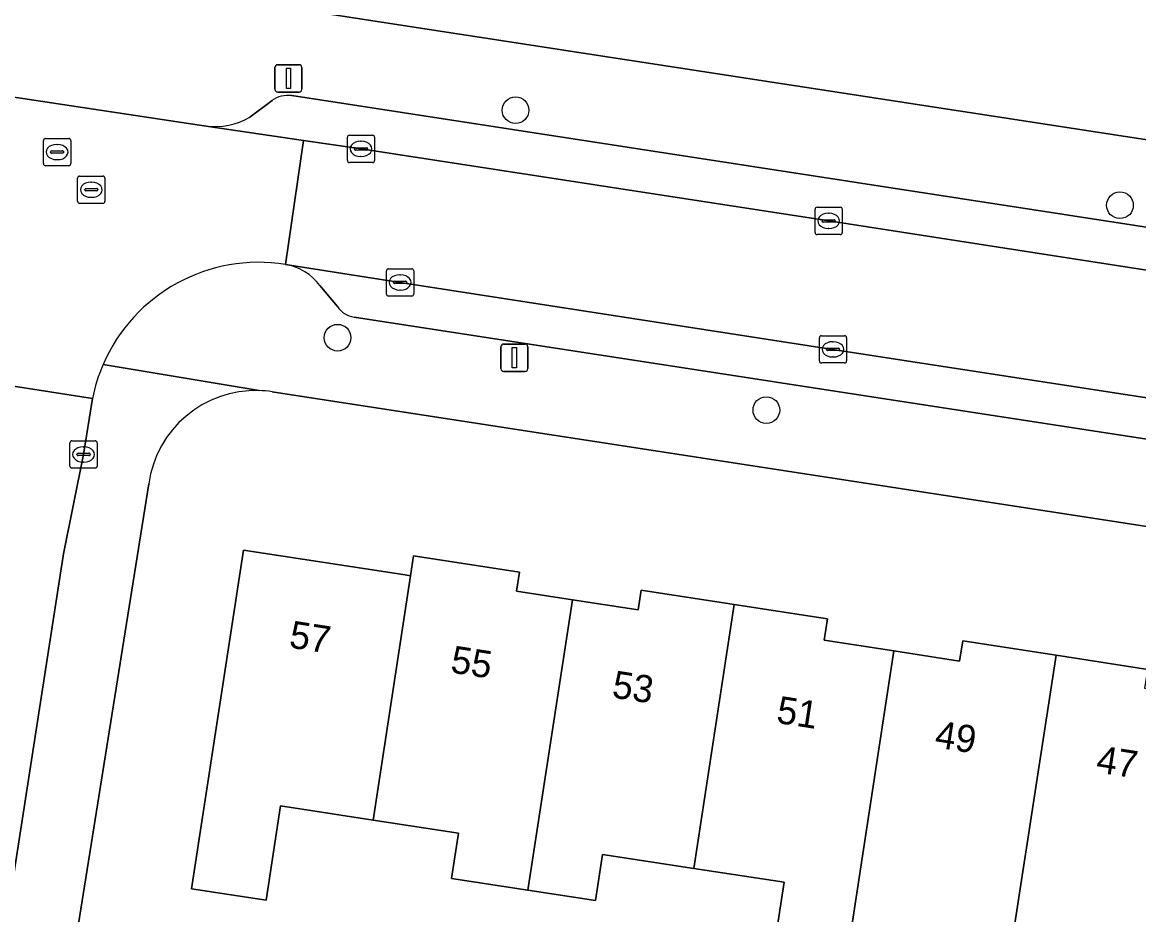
# Model space of a CAD drawing. Extents: x 161483 to 162250, y 379484 to 380833.
# Drawn here: x 161922.95 to 161963.9, y 380518.15 to 380550.89 of the extents above; entities that cross this region are included whole.
import ezdxf

# ---------------------------------------------------------------- set-up
doc = ezdxf.new("R2010")
doc.units = 0
for name, color, linetype in [('IMGEO_Boom', 7, 'Continuous'), ('IMGEO_Erf', 7, 'Continuous'), ('IMGEO_Kolk', 7, 'Continuous'), ('IMGEO_Lichtmast', 7, 'Continuous'), ('IMGEO_Pand', 7, 'Continuous'), ('IMGEO_Pand_nummerreeks', 7, 'Continuous'), ('IMGEO_Parkeervlak_open', 7, 'Continuous'), ('IMGEO_Rijbaan_lokaal_open', 7, 'Continuous'), ('IMGEO_Rioolput', 7, 'Continuous'), ('IMGEO_Voetpad_open', 7, 'Continuous')]:
    doc.layers.add(name, color=color, linetype=linetype)

msp = doc.modelspace()

# ---------------------------------------------------------------- linework, layer by layer
at = {"layer": 'IMGEO_Boom'}
for centre in [(161941.042, 380547.667), (161963.213, 380544.18), (161934.512, 380539.321), (161950.241, 380536.664)]:
    msp.add_circle(centre, 0.489, dxfattribs=at)
at = {"layer": 'IMGEO_Erf'}
for points in [[(161933.1, 380551.357), (161963.411, 380546.705), (161989.926, 380542.639)], [(162001.728, 380523.906), (162001.658, 380524.62), (162001.144, 380525.735), (162000.674, 380526.189), (162000.627, 380526.234), (162000, 380526.588), (161998.738, 380527.044), (161986.998, 380528.881), (161932.112, 380537.338)], [(161927.582, 380533.959), (161924.124, 380512.314)], [(161950.629, 380517.592), (161950.898, 380519.337), (161947.576, 380519.847), (161944.231, 380520.361), (161943.971, 380518.666), (161941.487, 380519.048), (161938.688, 380519.478), (161938.943, 380521.14), (161935.813, 380521.621), (161932.42, 380522.143), (161931.888, 380518.678), (161929.148, 380519.1), (161931.059, 380531.529), (161936.985, 380530.618), (161937.189, 380530.587), (161937.301, 380531.315), (161941.187, 380530.718), (161941.08, 380530.019), (161943.124, 380529.705), (161945.54, 380529.334), (161945.651, 380530.056), (161949.063, 380529.531), (161952.481, 380529.006), (161952.36, 380528.221), (161954.923, 380527.827), (161957.332, 380527.456), (161957.446, 380528.194), (161960.869, 380527.668), (161964.235, 380527.151)]]:
    msp.add_lwpolyline(points, dxfattribs=at)
for centre, radius, start, end in [((161931.515, 380533.412), 3.971, 88.3365, 172.0829), ((161931.527, 380533.506), 3.876, 81.3232, 88.4809)]:
    msp.add_arc(centre, radius, start, end, dxfattribs=at)
at = {"layer": 'IMGEO_Kolk'}
for p, q in [((161934.87, 380545.822), (161934.87, 380546.674)), ((161934.945, 380546.748), (161935.797, 380546.748)), ((161935.871, 380546.674), (161935.871, 380545.822)), ((161935.129, 380546.242), (161935.129, 380546.254)), ((161935.172, 380546.291), (161935.57, 380546.291)), ((161935.358, 380546.528), (161935.383, 380546.528)), ((161935.613, 380546.254), (161935.613, 380546.242)), ((161935.567, 380546.205), (161935.169, 380546.205)), ((161935.381, 380545.968), (161935.356, 380545.968)), ((161935.797, 380545.748), (161934.945, 380545.748)), ((161952.027, 380543.178), (161952.027, 380544.03)), ((161952.102, 380544.104), (161952.954, 380544.104)), ((161952.515, 380543.884), (161952.54, 380543.884)), ((161953.028, 380544.03), (161953.028, 380543.178)), ((161952.286, 380543.598), (161952.286, 380543.61)), ((161952.724, 380543.561), (161952.326, 380543.561)), ((161952.329, 380543.647), (161952.727, 380543.647)), ((161952.77, 380543.61), (161952.77, 380543.598)), ((161952.954, 380543.104), (161952.102, 380543.104)), ((161952.538, 380543.324), (161952.513, 380543.324)), ((161936.304, 380540.923), (161936.304, 380541.775)), ((161936.379, 380541.849), (161937.231, 380541.849)), ((161937.305, 380541.775), (161937.305, 380540.923)), ((161936.563, 380541.343), (161936.563, 380541.355)), ((161936.606, 380541.392), (161937.004, 380541.392)), ((161936.792, 380541.629), (161936.817, 380541.629)), ((161937.047, 380541.355), (161937.047, 380541.343)), ((161937.001, 380541.306), (161936.603, 380541.306)), ((161936.815, 380541.069), (161936.79, 380541.069)), ((161937.231, 380540.849), (161936.379, 380540.849)), ((161952.185, 380538.466), (161952.185, 380539.318)), ((161952.26, 380539.392), (161953.112, 380539.392)), ((161953.186, 380539.318), (161953.186, 380538.466)), ((161952.444, 380538.886), (161952.444, 380538.898)), ((161952.487, 380538.935), (161952.885, 380538.935)), ((161952.673, 380539.172), (161952.698, 380539.172)), ((161952.928, 380538.898), (161952.928, 380538.886)), ((161952.882, 380538.849), (161952.484, 380538.849)), ((161952.696, 380538.612), (161952.671, 380538.612)), ((161953.112, 380538.392), (161952.26, 380538.392)), ((161924.692, 380534.61), (161924.692, 380535.462)), ((161924.767, 380535.536), (161925.619, 380535.536)), ((161925.18, 380535.316), (161925.205, 380535.316)), ((161925.693, 380535.462), (161925.693, 380534.61)), ((161924.951, 380535.03), (161924.951, 380535.042)), ((161925.389, 380534.993), (161924.991, 380534.993)), ((161924.994, 380535.079), (161925.392, 380535.079)), ((161925.435, 380535.042), (161925.435, 380535.03)), ((161925.619, 380534.536), (161924.767, 380534.536)), ((161925.203, 380534.756), (161925.178, 380534.756))]:
    msp.add_line(p, q, dxfattribs=at)
for points in [[(161934.87, 380545.822), (161934.87, 380546.674)], [(161934.945, 380546.748), (161935.797, 380546.748)], [(161935.871, 380546.674), (161935.871, 380545.822)], [(161935.797, 380545.748), (161934.945, 380545.748)], [(161952.027, 380543.178), (161952.027, 380544.03)], [(161952.102, 380544.104), (161952.954, 380544.104)], [(161953.028, 380544.03), (161953.028, 380543.178)], [(161952.954, 380543.104), (161952.102, 380543.104)], [(161936.304, 380540.923), (161936.304, 380541.775)], [(161936.379, 380541.849), (161937.231, 380541.849)], [(161937.305, 380541.775), (161937.305, 380540.923)], [(161937.231, 380540.849), (161936.379, 380540.849)], [(161952.185, 380538.466), (161952.185, 380539.318)], [(161952.26, 380539.392), (161953.112, 380539.392)], [(161953.186, 380539.318), (161953.186, 380538.466)], [(161953.112, 380538.392), (161952.26, 380538.392)], [(161924.692, 380534.61), (161924.692, 380535.462)], [(161924.767, 380535.536), (161925.619, 380535.536)], [(161925.693, 380535.462), (161925.693, 380534.61)], [(161925.619, 380534.536), (161924.767, 380534.536)]]:
    msp.add_lwpolyline(points, dxfattribs=at)
for centre, radius, start, end in [((161934.947, 380546.672), 0.0765, 91.552, 178.448), ((161934.947, 380546.672), 0.0765, 91.552, 178.448), ((161935.795, 380546.672), 0.0765, 1.552, 88.448), ((161935.795, 380546.672), 0.0765, 1.552, 88.448), ((161935.169, 380546.251), 0.0403, 85.8775, 175.7526), ((161935.166, 380546.241), 0.0366, 178.938, 274.7102), ((161935.57, 380546.248), 0.043, 264.8664, 352.4533), ((161935.574, 380546.253), 0.0386, 1.7309, 96.639), ((161934.947, 380545.824), 0.0765, 181.552, 268.448), ((161934.947, 380545.824), 0.0765, 181.552, 268.448), ((161935.795, 380545.824), 0.0765, 271.552, 358.448), ((161935.795, 380545.824), 0.0765, 271.552, 358.448), ((161952.104, 380544.028), 0.0765, 91.552, 178.448), ((161952.104, 380544.028), 0.0765, 91.552, 178.448), ((161952.952, 380544.028), 0.0765, 1.552, 88.448), ((161952.952, 380544.028), 0.0765, 1.552, 88.448), ((161952.326, 380543.607), 0.0403, 85.8775, 175.7526), ((161952.323, 380543.597), 0.0366, 178.938, 274.7102), ((161952.727, 380543.604), 0.043, 264.8664, 352.4533), ((161952.731, 380543.609), 0.0386, 1.7309, 96.639), ((161952.104, 380543.18), 0.0765, 181.552, 268.448), ((161952.104, 380543.18), 0.0765, 181.552, 268.448), ((161952.952, 380543.18), 0.0765, 271.552, 358.448), ((161952.952, 380543.18), 0.0765, 271.552, 358.448), ((161936.381, 380541.773), 0.0765, 91.552, 178.448), ((161936.381, 380541.773), 0.0765, 91.552, 178.448), ((161937.229, 380541.773), 0.0765, 1.552, 88.448), ((161937.229, 380541.773), 0.0765, 1.552, 88.448), ((161936.603, 380541.352), 0.0403, 85.8775, 175.7526), ((161936.6, 380541.342), 0.0366, 178.938, 274.7102), ((161937.004, 380541.349), 0.043, 264.8664, 352.4533), ((161937.008, 380541.354), 0.0386, 1.7309, 96.639), ((161936.381, 380540.925), 0.0765, 181.552, 268.448), ((161936.381, 380540.925), 0.0765, 181.552, 268.448), ((161937.229, 380540.925), 0.0765, 271.552, 358.448), ((161937.229, 380540.925), 0.0765, 271.552, 358.448), ((161952.262, 380539.316), 0.0765, 91.552, 178.448), ((161952.262, 380539.316), 0.0765, 91.552, 178.448), ((161953.11, 380539.316), 0.0765, 1.552, 88.448), ((161953.11, 380539.316), 0.0765, 1.552, 88.448), ((161952.484, 380538.895), 0.0403, 85.8775, 175.7526), ((161952.481, 380538.885), 0.0366, 178.938, 274.7102), ((161952.885, 380538.892), 0.043, 264.8664, 352.4533), ((161952.889, 380538.897), 0.0386, 1.7309, 96.639), ((161952.262, 380538.468), 0.0765, 181.552, 268.448), ((161952.262, 380538.468), 0.0765, 181.552, 268.448), ((161953.11, 380538.468), 0.0765, 271.552, 358.448), ((161953.11, 380538.468), 0.0765, 271.552, 358.448), ((161924.769, 380535.46), 0.0765, 91.552, 178.448), ((161924.769, 380535.46), 0.0765, 91.552, 178.448), ((161925.617, 380535.46), 0.0765, 1.552, 88.448), ((161925.617, 380535.46), 0.0765, 1.552, 88.448), ((161924.991, 380535.039), 0.0403, 85.8775, 175.7526), ((161924.988, 380535.029), 0.0366, 178.938, 274.7102), ((161925.392, 380535.036), 0.043, 264.8664, 352.4533), ((161925.396, 380535.041), 0.0386, 1.7309, 96.639), ((161924.769, 380534.612), 0.0765, 181.552, 268.448), ((161924.769, 380534.612), 0.0765, 181.552, 268.448), ((161925.617, 380534.612), 0.0765, 271.552, 358.448), ((161925.617, 380534.612), 0.0765, 271.552, 358.448)]:
    msp.add_arc(centre, radius, start, end, dxfattribs=at)
for centre, major_axis, ratio, start_param, end_param in [((161935.357, 380546.248), (-0.387, 0.002), 0.722429, 4.712389, 7.853982), ((161935.382, 380546.248), (-0.39, 0.002), 0.717154, 1.570796, 4.712389), ((161952.514, 380543.604), (-0.387, 0.002), 0.722429, 4.712389, 7.853982), ((161952.539, 380543.604), (-0.39, 0.002), 0.717154, 1.570796, 4.712389), ((161936.791, 380541.349), (-0.387, 0.002), 0.722429, 4.712389, 7.853982), ((161936.816, 380541.349), (-0.39, 0.002), 0.717154, 1.570796, 4.712389), ((161952.672, 380538.892), (-0.387, 0.002), 0.722429, 4.712389, 7.853982), ((161952.697, 380538.892), (-0.39, 0.002), 0.717154, 1.570796, 4.712389), ((161925.179, 380535.036), (-0.387, 0.002), 0.722429, 4.712389, 7.853982), ((161925.204, 380535.036), (-0.39, 0.002), 0.717154, 1.570796, 4.712389)]:
    msp.add_ellipse(centre, major_axis=major_axis, ratio=ratio, start_param=start_param, end_param=end_param, dxfattribs=at)
at = {"layer": 'IMGEO_Lichtmast'}
for p, q in [((161932.212, 380548.434), (161932.212, 380549.234)), ((161932.212, 380549.234), (161932.212, 380548.434)), ((161932.312, 380549.334), (161933.102, 380549.334)), ((161933.102, 380549.334), (161932.312, 380549.334)), ((161933.202, 380549.234), (161933.202, 380548.434)), ((161933.202, 380548.434), (161933.202, 380549.234)), ((161933.102, 380548.334), (161932.312, 380548.334)), ((161932.312, 380548.334), (161933.102, 380548.334)), ((161940.502, 380538.185), (161940.502, 380538.985)), ((161940.502, 380538.985), (161940.502, 380538.185)), ((161940.602, 380539.085), (161941.392, 380539.085)), ((161941.392, 380539.085), (161940.602, 380539.085)), ((161941.492, 380538.985), (161941.492, 380538.185)), ((161941.492, 380538.185), (161941.492, 380538.985)), ((161941.392, 380538.085), (161940.602, 380538.085)), ((161940.602, 380538.085), (161941.392, 380538.085))]:
    msp.add_line(p, q, dxfattribs=at)
for points in [[(161932.632, 380549.209), (161932.782, 380549.209), (161932.782, 380548.459), (161932.632, 380548.459), (161932.632, 380549.209)], [(161940.922, 380538.96), (161941.072, 380538.96), (161941.072, 380538.21), (161940.922, 380538.21), (161940.922, 380538.96)]]:
    msp.add_lwpolyline(points, dxfattribs=at)
for centre, start, end in [((161932.312, 380549.234), 90, 180), ((161932.312, 380549.234), 90, 180), ((161933.102, 380549.234), 0, 90), ((161933.102, 380549.234), 360, 90), ((161932.312, 380548.434), 180, 270), ((161932.312, 380548.434), 180, 270), ((161933.102, 380548.434), 270, 0), ((161933.102, 380548.434), 270, 0), ((161940.602, 380538.985), 90, 180), ((161940.602, 380538.985), 90, 180), ((161941.392, 380538.985), 0, 90), ((161941.392, 380538.985), 360, 90), ((161940.602, 380538.185), 180, 270), ((161940.602, 380538.185), 180, 270), ((161941.392, 380538.185), 270, 0), ((161941.392, 380538.185), 270, 0)]:
    msp.add_arc(centre, 0.1, start, end, dxfattribs=at)
at = {"layer": 'IMGEO_Pand'}
for points in [[(161937.189, 380530.587), (161936.985, 380530.618), (161931.059, 380531.529), (161929.148, 380519.1), (161931.888, 380518.678), (161932.42, 380522.143), (161935.813, 380521.621)], [(161943.124, 380529.705), (161941.08, 380530.019), (161941.187, 380530.718), (161937.301, 380531.315), (161937.189, 380530.587), (161935.813, 380521.621), (161938.943, 380521.14), (161938.688, 380519.478), (161941.487, 380519.048)], [(161941.487, 380519.048), (161943.971, 380518.666), (161944.231, 380520.361), (161947.576, 380519.847), (161949.063, 380529.531), (161945.651, 380530.056), (161945.54, 380529.334), (161943.124, 380529.705)], [(161953.288, 380517.183), (161954.923, 380527.827), (161952.36, 380528.221), (161952.481, 380529.006), (161949.063, 380529.531), (161947.576, 380519.847), (161950.898, 380519.337), (161950.629, 380517.592)], [(161960.869, 380527.668), (161957.446, 380528.194), (161957.332, 380527.456), (161954.923, 380527.827), (161953.288, 380517.183), (161956.197, 380516.736), (161959.162, 380516.28), (161959.381, 380517.981)], [(161966.695, 380526.052), (161964.127, 380526.446), (161964.235, 380527.151), (161960.869, 380527.668), (161959.381, 380517.981), (161959.162, 380516.28), (161959.156, 380516.237), (161965.048, 380515.332)]]:
    msp.add_lwpolyline(points, close=True, dxfattribs=at)
at = {"layer": 'IMGEO_Parkeervlak_open'}
for points in [[(161932.106, 380548.019), (161931.292, 380547.414)], [(161998.077, 380538.155), (161932.83, 380548.205)], [(161929.69, 380547.086), (161933.264, 380546.55), (161935.372, 380546.247), (161952.528, 380543.603), (161973.878, 380540.297), (161995.793, 380536.963), (162000, 380536.329), (162000.684, 380536.226), (162000, 380536.452), (161999.367, 380536.946), (161998.747, 380537.733)], [(161999.874, 380531.653), (161994.763, 380532.455), (161975.164, 380535.431), (161952.685, 380538.893), (161936.805, 380541.351), (161932.606, 380542.007)], [(161933.865, 380541.239), (161934.51, 380540.47)], [(161935.118, 380540.075), (161996.932, 380530.558)]]:
    msp.add_lwpolyline(points, dxfattribs=at)
for centre, radius, start, end in [((161932.707, 380547.181), 1.032, 83.1651, 125.651), ((161930.026, 380549.523), 2.46, 262.1609, 300.9812), ((161932.256, 380540.017), 2.021, 37.214, 80.019), ((161935.228, 380540.91), 0.843, 211.5112, 262.4676)]:
    msp.add_arc(centre, radius, start, end, dxfattribs=at)
at = {"layer": 'IMGEO_Rijbaan_lokaal_open'}
for points in [[(161933.264, 380546.55), (161929.69, 380547.086), (161918.825, 380548.717), (161914.845, 380549.326), (161914.156, 380544.809), (161914.419, 380544.768), (161915.431, 380544.596)], [(161932.606, 380542.007), (161933.264, 380546.55)], [(161921.012, 380508.607), (161921.604, 380512.685), (161922.248, 380517.116), (161924.453, 380531.388), (161925.192, 380535.036), (161925.521, 380537.092), (161920.649, 380537.844), (161920.428, 380536.339), (161918.926, 380527.722), (161916.815, 380514.45), (161916.654, 380513.285), (161916.253, 380510.374), (161916.11, 380509.645)], [(161920.649, 380537.844), (161925.521, 380537.092)]]:
    msp.add_lwpolyline(points, dxfattribs=at)
msp.add_lwpolyline([(161933.264, 380546.55), (161932.606, 380542.007), (161936.805, 380541.351), (161952.685, 380538.893), (161975.164, 380535.431), (161994.763, 380532.455), (161999.874, 380531.653), (162000, 380531.633), (162000, 380531.772), (162000.684, 380536.226), (162000, 380536.329), (161995.793, 380536.963), (161973.878, 380540.297), (161952.528, 380543.603), (161935.372, 380546.247)], close=True, dxfattribs=at)
for centre, radius, start, end in [((161931.617, 380535.869), 6.217, 80.8484, 156.6311), ((161931.625, 380535.864), 6.226, 156.6182, 168.6265)]:
    msp.add_arc(centre, radius, start, end, dxfattribs=at)
at = {"layer": 'IMGEO_Rioolput'}
for p, q in [((161923.721, 380545.706), (161923.721, 380546.558)), ((161923.796, 380546.632), (161924.648, 380546.632)), ((161924.209, 380546.412), (161924.234, 380546.412)), ((161924.722, 380546.558), (161924.722, 380545.706)), ((161923.98, 380546.126), (161923.98, 380546.138)), ((161924.418, 380546.089), (161924.02, 380546.089)), ((161924.023, 380546.175), (161924.421, 380546.175)), ((161924.232, 380545.852), (161924.207, 380545.852)), ((161924.464, 380546.138), (161924.464, 380546.126)), ((161924.648, 380545.632), (161923.796, 380545.632)), ((161924.975, 380544.324), (161924.975, 380545.176)), ((161925.05, 380545.25), (161925.902, 380545.25)), ((161925.463, 380545.03), (161925.488, 380545.03)), ((161925.976, 380545.176), (161925.976, 380544.324)), ((161925.234, 380544.744), (161925.234, 380544.756)), ((161925.672, 380544.707), (161925.274, 380544.707)), ((161925.277, 380544.793), (161925.675, 380544.793)), ((161925.718, 380544.756), (161925.718, 380544.744)), ((161925.902, 380544.25), (161925.05, 380544.25)), ((161925.486, 380544.47), (161925.461, 380544.47))]:
    msp.add_line(p, q, dxfattribs=at)
for points in [[(161923.721, 380545.706), (161923.721, 380546.558)], [(161923.796, 380546.632), (161924.648, 380546.632)], [(161924.722, 380546.558), (161924.722, 380545.706)], [(161924.648, 380545.632), (161923.796, 380545.632)], [(161924.975, 380544.324), (161924.975, 380545.176)], [(161925.05, 380545.25), (161925.902, 380545.25)], [(161925.976, 380545.176), (161925.976, 380544.324)], [(161925.902, 380544.25), (161925.05, 380544.25)]]:
    msp.add_lwpolyline(points, dxfattribs=at)
for centre, radius, start, end in [((161923.798, 380546.556), 0.0765, 91.552, 178.448), ((161923.798, 380546.556), 0.0765, 91.552, 178.448), ((161924.646, 380546.556), 0.0765, 1.552, 88.448), ((161924.646, 380546.556), 0.0765, 1.552, 88.448), ((161924.02, 380546.135), 0.0403, 85.8775, 175.7526), ((161924.017, 380546.125), 0.0366, 178.938, 274.7102), ((161924.421, 380546.132), 0.043, 264.8664, 352.4533), ((161924.425, 380546.137), 0.0386, 1.7309, 96.639), ((161923.798, 380545.708), 0.0765, 181.552, 268.448), ((161923.798, 380545.708), 0.0765, 181.552, 268.448), ((161924.646, 380545.708), 0.0765, 271.552, 358.448), ((161924.646, 380545.708), 0.0765, 271.552, 358.448), ((161925.052, 380545.174), 0.0765, 91.552, 178.448), ((161925.052, 380545.174), 0.0765, 91.552, 178.448), ((161925.9, 380545.174), 0.0765, 1.552, 88.448), ((161925.9, 380545.174), 0.0765, 1.552, 88.448), ((161925.274, 380544.753), 0.0403, 85.8775, 175.7526), ((161925.271, 380544.743), 0.0366, 178.938, 274.7102), ((161925.675, 380544.75), 0.043, 264.8664, 352.4533), ((161925.679, 380544.755), 0.0386, 1.7309, 96.639), ((161925.052, 380544.326), 0.0765, 181.552, 268.448), ((161925.052, 380544.326), 0.0765, 181.552, 268.448), ((161925.9, 380544.326), 0.0765, 271.552, 358.448), ((161925.9, 380544.326), 0.0765, 271.552, 358.448)]:
    msp.add_arc(centre, radius, start, end, dxfattribs=at)
for centre, major_axis, ratio, start_param, end_param in [((161924.208, 380546.132), (-0.387, 0.002), 0.722429, 4.712389, 7.853982), ((161924.233, 380546.132), (-0.39, 0.002), 0.717154, 1.570796, 4.712389), ((161925.462, 380544.75), (-0.387, 0.002), 0.722429, 4.712389, 7.853982), ((161925.487, 380544.75), (-0.39, 0.002), 0.717154, 1.570796, 4.712389)]:
    msp.add_ellipse(centre, major_axis=major_axis, ratio=ratio, start_param=start_param, end_param=end_param, dxfattribs=at)
at = {"layer": 'IMGEO_Voetpad_open'}
for points in [[(162007.859, 380539.593), (162001.608, 380540.698), (162000, 380540.965), (161989.926, 380542.639), (161963.411, 380546.705), (161933.1, 380551.357), (161926.533, 380552.341), (161923.744, 380552.759), (161920.738, 380553.21), (161887.994, 380558.235), (161850.616, 380563.993), (161845.302, 380564.812), (161842.113, 380565.304), (161840.43, 380565.564), (161785.522, 380574.037), (161759.686, 380578.007), (161759.209, 380578.08), (161755.449, 380578.66), (161754.33, 380578.833), (161724.808, 380583.386), (161711.262, 380585.528)], [(161918.825, 380548.717), (161929.69, 380547.086)], [(161931.292, 380547.414), (161932.106, 380548.019)], [(161932.83, 380548.205), (161998.077, 380538.155)], [(161934.51, 380540.47), (161933.865, 380541.239)], [(161996.932, 380530.558), (161935.118, 380540.075)], [(161931.63, 380537.381), (161925.91, 380538.335)], [(161925.91, 380538.335), (161931.63, 380537.381)], [(161932.112, 380537.338), (161986.998, 380528.881), (161998.738, 380527.044), (162000, 380526.588), (162000.627, 380526.234), (162000.674, 380526.189), (162005.228, 380525.716)], [(161925.521, 380537.092), (161925.192, 380535.036), (161924.453, 380531.388), (161922.248, 380517.116), (161921.604, 380512.685), (161924.124, 380512.314), (161927.582, 380533.959)]]:
    msp.add_lwpolyline(points, dxfattribs=at)
for centre, radius, start, end in [((161932.707, 380547.181), 1.032, 83.1651, 125.651), ((161930.026, 380549.523), 2.46, 262.1609, 300.9812), ((161931.617, 380535.869), 6.217, 80.8484, 156.6311), ((161932.256, 380540.017), 2.021, 37.214, 80.019), ((161935.228, 380540.91), 0.843, 211.5112, 262.4676), ((161931.625, 380535.864), 6.226, 156.6182, 168.6265), ((161931.515, 380533.412), 3.971, 88.3365, 172.0829), ((161931.527, 380533.506), 3.876, 81.3232, 88.4809)]:
    msp.add_arc(centre, radius, start, end, dxfattribs=at)

# ---------------------------------------------------------------- texts
at = {"layer": 'IMGEO_Pand_nummerreeks'}
for s, rotation, p in [('57', 351.2108, (161932.701, 380527.955)), ('55', 351.2108, (161938.622, 380527.04)), ('53', 351.2104, (161944.543, 380526.125)), ('51', 351.2104, (161950.576, 380525.193)), ('49', 351.2108, (161956.385, 380524.293)), ('47', 351.2108, (161962.306, 380523.378))]:
    msp.add_text(s, height=1, rotation=rotation, dxfattribs=at).set_placement(p)

doc.saveas('drawing.dxf')
